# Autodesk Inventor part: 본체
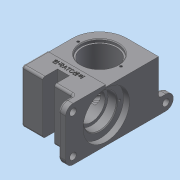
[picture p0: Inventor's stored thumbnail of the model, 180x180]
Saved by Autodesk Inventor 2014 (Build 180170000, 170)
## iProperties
Created: 2023-09
Part Number: 본체
Material: 일반
Document SubType Name: Modeling
Designer: dg
Density: 1 g/cm^3
Appearance: 기본값
Author: dg
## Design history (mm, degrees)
sketch "스케치1"
  geometry: L1 (0, 0)-(-80, 0); L2 (-80, 0)-(-80, 106); L3 (-80, 106)-(0, 106); L4 (0, 106)-(0, 0); 1 further point
  constraints: 8 end point, 2 parallel, 1 coincident, 1 horizontal, 1 perpendicular
  dimensions: "d0" = 106 distance of L3.end L1.start; "d1" = 80 distance of L2.end L3.end
extrude "돌출1" new body sketch "스케치1" distance "d2" = 72; taper "d3" = 0 deg
fillet "모깎기1" dims "d4" = 37
node "작업 평면1"
sketch "스케치3"
  geometry: L1 (-43, 106)-(0, 106) reference; L2 (0, 106)-(0, 0) reference; L3 (0, 0)-(-80, 0) reference; L4 (-80, 0)-(-80, 69) reference; L5 (-80, 35)-(0, 35); L6 (-80, 66.5)-(-77, 66.5); L7 (-77, 66.5)-(-77, 57.5); L8 (-77, 57.5)-(-65, 57.5); L9 (-65, 57.5)-(-65, 53.5); L10 (-65, 53.5)-(-20, 53.5); L11 (-20, 53.5)-(-20, 57.5); L12 (-20, 57.5)-(-8, 57.5); L13 (-8, 57.5)-(-8, 66.5); L14 (-8, 66.5)-(0, 66.5); A1 r 37 centre (-43, 69) between (-43, 106) and (-80, 69) reference
  constraints: 20 end point, 5 parallel, 4 point on line, 3 perpendicular, 2 horizontal, 2 horizontal alignment, 1 collinear
  dimensions: "d5" = 35 distance from line of L3 L5.start; "d6" = 3 distance of L6.start L6.end; "d7" = 12 distance of L7.end L8.end; "d8" = 8 distance of L13.end L14.end; "d9" = 37 diameter of L10 L5; "d10" = 45 diameter of L8 L5; "d11" = 63 diameter of L6 L5
revolve "회전1" sketch "스케치3" stored, may be unused: angle "d12" = 90 deg
sketch "스케치4"
  geometry: L1 (-80, 0)-(0, 0) reference; L2 (0, 0)-(0, 106) reference; L3 (-51, 0)-(-35, 0); L4 (-35, 0)-(-35, 20); L5 (-35, 20)-(-51, 20); L6 (-51, 20)-(-51, 0); 1 further point
  constraints: 8 end point, 2 parallel, 1 horizontal, 1 midpoint, 1 perpendicular, 1 point on line
  dimensions: "d13" = 16 distance of L4.end L5.end; "d14" = 20 distance of L5.end L3.start; "d15" = 43 distance from line of point (-43, 20) L2
extrude "돌출2" cut sketch "스케치4" stored distance "d16" = 72; taper "d17" = 0 deg
sketch "스케치5"
  geometry: L1 (-72, 0)-(0, 0); L2 (0, 0)-(0, -20); L3 (0, -20)-(-72, -20); L4 (-72, -20)-(-72, 0); 1 further point
  constraints: 8 end point, 2 parallel, 1 horizontal, 1 perpendicular, 1 vertical alignment
  dimensions: "d18" = 20 distance of L1.end L2.end
extrude "돌출3" join sketch "스케치5" distance "d19" = 10; taper "d20" = 0 deg
sketch "스케치6"
  geometry: L1 (0, 0)-(0, -20) reference; L2 (0, -20)-(72, -20) reference; 2 further points
  constraints: 1 horizontal alignment
  dimensions: "d21" = 52 distance of point (62, -10) point (10, -10); "d22" = 10 distance from line of L1 point (10, -10); "d23" = 10 distance from line of L2 point (10, -10)
hole "구멍1" sketch "스케치6" at (10, -10), (62, -10) diameter "d24" = 9; stored, may be unused: countersink angle "d28" = 90 deg, drill point angle "d30" = 118 deg; dims "d25" = 6, "d26" = 4, "d27" = 2, "d29" = 8
fillet "모깎기2" dims "d31" = 10
node "작업 평면2"
node "작업 평면3"
sketch "스케치12"
  geometry: L1 (0, 0)-(52, 0) reference; L2 (62, 126)-(-10, 126) reference; L3 (62, 126)-(62, 136); L4 (42, 136)-(42, 126); A1 r 10 centre (52, 136) between (62, 136) and (42, 136); 3 further points
  constraints: 4 end point, 2 perpendicular, 2 point on circle, 2 tangent, 1 centre point, 1 coincident, 1 point on line
  dimensions: "d55" = 10 radius of A1; "d56" = 146 dimension on A1 L1
extrude "돌출5" join sketch "스케치12" distance "d57" = 10; taper "d58" = 0 deg
hole "구멍2" sketch "스케치12" diameter "d59" = 9; stored, may be unused: countersink angle "d63" = 90 deg, drill point angle "d65" = 118 deg; dims "d60" = 6, "d61" = 4, "d62" = 2, "d64" = 8
sketch "스케치13"
  geometry: C1 r 31.5 at (0, 0) reference; 2 further points
  constraints: 1 vertical alignment
  dimensions: "d66" = 26 distance of C1.centre point (0, 26)
hole "구멍3" sketch "스케치13" at (0, 26) diameter "d67" = 3.242; stored, may be unused: countersink angle "d71" = 90 deg, drill point angle "d73" = 118 deg; dims "d68" = 8, "d69" = 4, "d70" = 2, "d72" = 10
sketch "스케치14"
  geometry: C1 r 22.5 at (0, 0) reference; 2 further points
  constraints: 1 vertical alignment
  dimensions: "d77" = 26 distance of C1.centre point (0, 26)
hole "구멍4" sketch "스케치14" at (0, 26) diameter "d78" = 3.242; stored, may be unused: countersink angle "d82" = 90 deg, drill point angle "d84" = 118 deg; dims "d79" = 8, "d80" = 4, "d81" = 2, "d83" = 10
node "작업 평면4"
sketch "스케치15"
  geometry: L1 (15.172, 40)-(-10, 40) reference; L2 (-10, 40)-(-10, 126) reference; L3 (-10, 126)-(62, 126) reference; L4 (62, 126)-(62, 40) reference; L5 (62, 40)-(36.828, 40) reference; L6 (-10, 89)-(62, 89); L7 (-10, 114)-(-3, 114); L8 (-3, 114)-(-3, 112); L9 (-3, 112)-(37, 112); L10 (37, 112)-(37, 106.5); L11 (37, 106.5)-(52, 106.5); L12 (52, 106.5)-(52, 104.5); L13 (52, 104.5)-(56, 104.5); L14 (56, 104.5)-(56, 89); A1 r 18.5 centre (26, 55) between (36.828, 40) and (15.172, 40) reference; 1 further point
  constraints: 18 end point, 8 parallel, 4 point on line, 1 perpendicular
  dimensions: "d86" = 34 distance from line of A1.centre L6; "d87" = 7 distance of L7.start L7.end; "d88" = 40 distance of L8.end L9.end; "d89" = 15 distance of L10.end L11.end; "d90" = 4 distance of L12.end L13.end; "d91" = 50 diameter of L7 L6; "d92" = 46 diameter of L9 L6; "d93" = 35 diameter of L11 L6; "d94" = 31 diameter of L13 L6
revolve "회전4" sketch "스케치15" stored, may be unused: angle "d95" = 90 deg
sketch "스케치16"
  geometry: L1 (0, 106)-(-43, 106) reference; L2 (-43, 106)-(0, 106) reference; L3 (0, 106)-(0, -10) reference; L4 (0, -10)-(-10, -10) reference; L5 (-10, -10)-(-10, 0) reference; L6 (-10, 0)-(-35, 0) reference; L7 (-35, 0)-(-35, 20) reference; L8 (-35, 20)-(-51, 20) reference; L9 (-51, 20)-(-51, 0) reference; L10 (-51, 0)-(-80, 0) reference; L11 (-80, 0)-(-80, 69) reference; L12 (-80, 34)-(0, 34); C1 r 25 at (-43, 69) reference; C2 r 25 at (-43, 69) reference; A1 r 37 centre (-43, 69) between (-43, 106) and (-80, 69) reference; 1 further point
  constraints: 2 end point, 2 point on line, 1 perpendicular
  dimensions: "d99" = 72 distance between parallel lines of L12 L1
extrude "돌출6" cut sketch "스케치16" distance "d100" = 3; taper "d101" = 0 deg
sketch "스케치17"
  geometry: C1 r 25 at (-43, 69) reference; 2 further points
  constraints: 1 horizontal alignment
  dimensions: "d102" = 29 distance of point (-14, 69) C1.centre
hole "구멍5" sketch "스케치17" at (-14, 69) diameter "d103" = 3.242; stored, may be unused: countersink angle "d107" = 90 deg, drill point angle "d109" = 118 deg; dims "d104" = 8, "d105" = 4, "d106" = 2, "d108" = 10
sketch "스케치18"
  geometry: L1 (-80, 0)-(-51, 0) reference; C1 r 15.5 at (-43, 69) reference; 2 further points
  constraints: 1 vertical alignment, 1 other
  dimensions: "d113" = 27 distance from line of L1 point (-43, 27)
feature "엠보싱1" sketch "스케치18" dims "d114" = 0.5, "d115" = 0
chamfer "모따기1" distance "d116" = 1; stored, may be unused: second distance "d117" = 2, angle "d118" = 45 deg
fillet "모깎기3" dims "d119" = 0.3
fillet "모깎기4" dims "d120" = 3
fillet "모깎기5" dims "d121" = 3
fillet "모깎기6" dims "d122" = 3
fillet "모깎기7" dims "d123" = 3
fillet "모깎기8" dims "d124" = 3
sketch "스케치19"
  geometry: L1 (51, -10)-(51, -62) reference; L2 (20.776, -47)-(-4.776, -47) reference; L3 (31, -7)-(-15, -7) reference; L4 (-14, -13.5)-(-14, -58.5) reference; L5 (-25, -58.5)-(-25, -13.5) reference; L6 (16, -72)-(0, -72) reference; 3 further points
  constraints: 1 horizontal alignment, 1 vertical alignment
  dimensions: "d125" = 43 distance from line of L1 point (8, -11); "d126" = 50 distance of point (8, -61) point (8, -11); "d127" = 11 distance from line of L6 point (8, -61)
hole "구멍6" sketch "스케치19" at (8, -11), (8, -61) diameter "d128" = 3.242; stored, may be unused: countersink angle "d132" = 82 deg, drill point angle "d134" = 118 deg; dims "d129" = 8, "d130" = 3.023, "d131" = 2, "d133" = 10
node "솔리드1"
pattern_circular "원형 패턴1" dims angle "d75" = 360 deg
pattern_circular "원형 패턴2" dims angle "d97" = 360 deg
pattern_circular "원형 패턴3" dims angle "d111" = 360 deg
node "투영된 루프1"
node "투영된 루프2"
node "절단 모서리 투영1"
node "절단 모서리 투영5"
node "절단 모서리 투영6"
other parameters: "d85" = -43
